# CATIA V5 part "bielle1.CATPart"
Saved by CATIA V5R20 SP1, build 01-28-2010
Part number: bielle3
Bounding box of the stored display mesh (mm): x 19.939 to 87, y -10 to 5, z 28.093 to 41.907
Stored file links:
  E:\EDELI\gcausse\Edeli_2012_679_gcausse\bielle1.CATPart
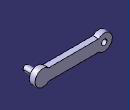
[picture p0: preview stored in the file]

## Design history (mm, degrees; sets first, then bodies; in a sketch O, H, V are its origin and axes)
Parameters
  long = 0.0530612
  diamtrou = 0.005
Body1 (main body)
  Sketch1 on zx-plane, origin (0, 0, 0), H (-1, 0, 0), V (0, 0, 1)
    line L1 (-31.8378, 40) -> (-75.101, 40)
    line L2 (-31.8378, 30) -> (-75.101, 30)
    arc A1 centre (-26.9388, 35) radius 7 from (-31.8378, 40) to (-31.8378, 30) cw
    point P5 (-26.9388, 35)
    point P6 (-22.0398, 30)
    arc A2 centre (-80, 35) radius 7 from (-75.101, 40) to (-75.101, 30) ccw
    point P7 (-80, 35)
    circle A3 centre (-26.9388, 35) radius 2.5
    distance P7 L1 = 5
    distance P5 L2 = 5
    distance L2 L1 = 10
    radius A1 = 7
    radius A2 = 7
    distance P5 P7 = 53.0612 {= long}
    radius A3 = 2.5
    horizontal: L1 H, L2 H
    coincidence: A1 P6, P6 L2
  Pad1: profile Sketch1, direction (0, 1, 0), length 5
  Sketch2 on start face of Pad1, origin (0, 0, 0), H (1, 0, 0), V (0, 0, 1)
    circle A1 centre (80, 35) radius 2.5
    reference projected arc E1 centre (80, 35) radius 7 from (75.101, 30) to (75.101, 40) ccw from edge [start face of Pad1 | face of Pad1 from Sketch1.A2]
    reference projected arc E2 centre (80, 35) radius 7 from (75.101, 30) to (75.101, 40) ccw from edge [start face of Pad1 | face of Pad1 from Sketch1.A2]
    radius A1 = 2.5
    radius E2 = 7 (reference)
    concentricity: A1 E1
  Pad2: profile Sketch2, direction (0, -1, 0), length 10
